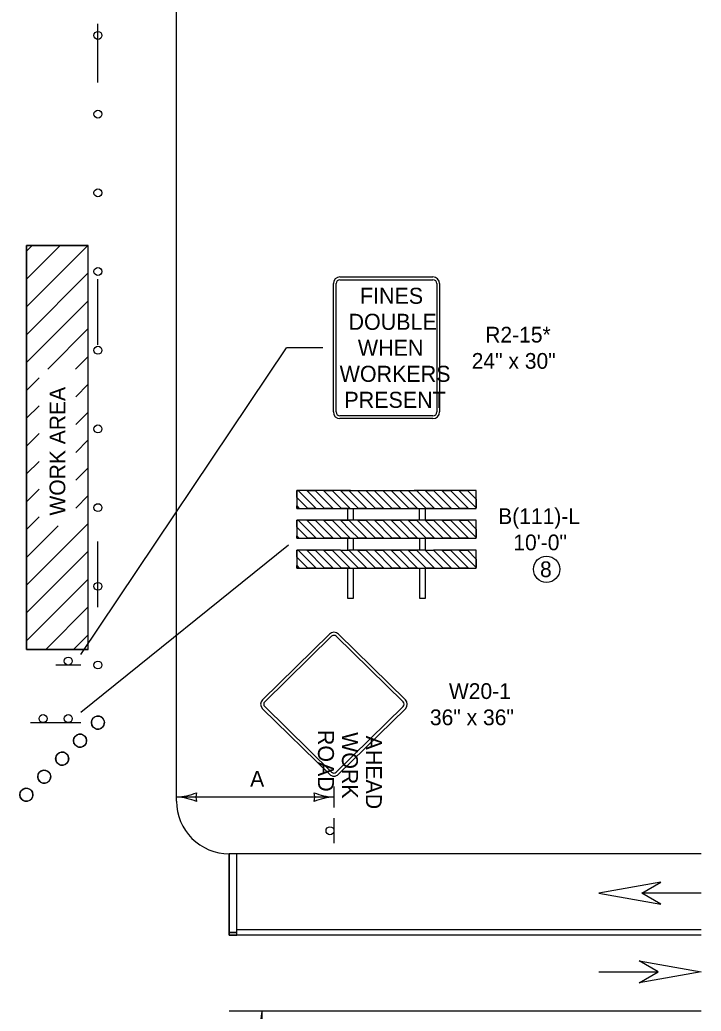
# Model space of a CAD drawing. Extents: x 49991.4 to 50021, y 49987.6 to 50011.4.
# Drawn here: x 50001.828 to 50004.426, y 49992.224 to 49996.003 of the extents above; entities that cross this region are included whole.
import ezdxf

# ---------------------------------------------------------------- set-up
doc = ezdxf.new("R2010")
doc.units = 0
for name, color, linetype in [('Level 1', 7, 'Continuous'), ('Level 2', 7, 'Continuous'), ('Level 3', 7, 'Continuous')]:
    doc.layers.add(name, color=color, linetype=linetype)

msp = doc.modelspace()

# ---------------------------------------------------------------- linework, layer by layer
at = {"layer": 'Level 1'}
for p, q in [((50002.4258, 49995.0313), (50002.4258, 49998.8719)), ((50002.1259, 49995.764), (50002.1259, 49995.988)), ((50001.8536, 49993.6029), (50001.8536, 49995.1428)), ((50001.8536, 49995.1428), (50002.0891, 49995.1428)), ((50001.8536, 49995.1207), (50001.8757, 49995.1428)), ((50001.8536, 49995.0146), (50001.9818, 49995.1428)), ((50001.8536, 49994.9086), (50002.0878, 49995.1428)), ((50002.0891, 49993.6029), (50002.0891, 49995.1428)), ((50001.8536, 49994.8025), (50002.0891, 49995.038)), ((50002.1259, 49994.764), (50002.1259, 49995.014)), ((50002.4258, 49993.024), (50002.4258, 49995.0313)), ((50003.0487, 49995.0228), (50003.4031, 49995.0228)), ((50003.0487, 49995.0123), (50003.4031, 49995.0123)), ((50003.2259, 49995.0228), (50003.2259, 49995.0228)), ((50003.0234, 49994.5081), (50003.0234, 49994.9975)), ((50003.034, 49994.5081), (50003.034, 49994.9975)), ((50003.4179, 49994.9975), (50003.4179, 49994.5081)), ((50003.4285, 49994.9975), (50003.4285, 49994.5081)), ((50001.8536, 49994.6964), (50002.0891, 49994.9319)), ((50001.9345, 49994.6712), (50002.0891, 49994.8259)), ((50002.0406, 49994.6712), (50002.0891, 49994.7198)), ((50001.8536, 49994.5904), (50001.9014, 49994.6381)), ((50002.0414, 49994.566), (50002.0891, 49994.6137)), ((50001.8536, 49994.4843), (50001.9014, 49994.5321)), ((50002.0414, 49994.4599), (50002.0891, 49994.5077)), ((50003.4031, 49994.4933), (50003.0487, 49994.4933)), ((50003.4031, 49994.4827), (50003.0487, 49994.4827)), ((50001.8536, 49994.3783), (50001.9014, 49994.426)), ((50002.0414, 49994.3539), (50002.0891, 49994.4016)), ((50001.8536, 49994.2722), (50001.9014, 49994.3199)), ((50002.0414, 49994.2478), (50002.0891, 49994.2956)), ((50001.8536, 49994.1661), (50001.9014, 49994.2139)), ((50002.0414, 49994.1417), (50002.0891, 49994.1895)), ((50002.9257, 49994.1407), (50002.884, 49994.1824)), ((50002.9257, 49994.1407), (50002.884, 49994.1824)), ((50002.9579, 49994.1407), (50002.8895, 49994.2091)), ((50002.8895, 49994.2091), (50002.9579, 49994.1407)), ((50002.9902, 49994.1407), (50002.9218, 49994.2091)), ((50002.9902, 49994.1407), (50002.9218, 49994.2091)), ((50003.0225, 49994.1407), (50002.9541, 49994.2091)), ((50002.9541, 49994.2091), (50003.0225, 49994.1407)), ((50003.0547, 49994.1407), (50002.9863, 49994.2091)), ((50003.0547, 49994.1407), (50002.9863, 49994.2091)), ((50003.0869, 49994.1407), (50003.0185, 49994.2091)), ((50003.0185, 49994.2091), (50003.0869, 49994.1407)), ((50003.1192, 49994.1407), (50003.0508, 49994.2091)), ((50003.1514, 49994.1407), (50003.083, 49994.2091)), ((50003.083, 49994.2091), (50003.1229, 49994.2091)), ((50003.1034, 49994.2091), (50003.3485, 49994.2091)), ((50003.1836, 49994.1407), (50003.1152, 49994.2091)), ((50003.2158, 49994.1407), (50003.1474, 49994.2091)), ((50003.248, 49994.1407), (50003.1796, 49994.2091)), ((50003.2802, 49994.1407), (50003.2118, 49994.2091)), ((50003.3124, 49994.1407), (50003.244, 49994.2091)), ((50003.3446, 49994.1407), (50003.2762, 49994.2091)), ((50003.377, 49994.1407), (50003.3086, 49994.2091)), ((50003.3627, 49994.2091), (50003.3314, 49994.2091)), ((50003.4093, 49994.1407), (50003.3409, 49994.2091)), ((50003.4415, 49994.1407), (50003.3732, 49994.2091)), ((50003.4415, 49994.1407), (50003.3732, 49994.2091)), ((50003.4737, 49994.1407), (50003.4054, 49994.2091)), ((50003.4054, 49994.2091), (50003.4737, 49994.1407)), ((50003.506, 49994.1407), (50003.4376, 49994.2091)), ((50003.506, 49994.1407), (50003.4376, 49994.2091)), ((50003.5382, 49994.1407), (50003.4698, 49994.2091)), ((50003.4698, 49994.2091), (50003.5382, 49994.1407)), ((50003.5679, 49994.1432), (50003.5021, 49994.2091)), ((50003.5679, 49994.1432), (50003.5021, 49994.2091)), ((50003.5679, 49994.1755), (50003.5343, 49994.2091)), ((50003.5343, 49994.2091), (50003.5679, 49994.1755)), ((50002.8935, 49994.1407), (50002.884, 49994.1502)), ((50002.884, 49994.1502), (50002.8935, 49994.1407)), ((50001.8536, 49994.0601), (50001.9014, 49994.1078)), ((50003.1005, 49994.0951), (50003.1005, 49994.1407)), ((50003.3513, 49994.0951), (50003.3513, 49994.1407)), ((50001.8536, 49993.8479), (50002.0891, 49994.0834)), ((50001.8536, 49993.954), (50001.9741, 49994.0744)), ((50002.9257, 49994.0267), (50002.884, 49994.0685)), ((50002.9257, 49994.0267), (50002.884, 49994.0685)), ((50002.9579, 49994.0267), (50002.8895, 49994.0951)), ((50002.8895, 49994.0951), (50002.9579, 49994.0267)), ((50002.9902, 49994.0267), (50002.9218, 49994.0951)), ((50002.9902, 49994.0267), (50002.9218, 49994.0951)), ((50003.0225, 49994.0267), (50002.9541, 49994.0951)), ((50002.9541, 49994.0951), (50003.0225, 49994.0267)), ((50003.0547, 49994.0267), (50002.9863, 49994.0951)), ((50003.0547, 49994.0267), (50002.9863, 49994.0951)), ((50003.0869, 49994.0267), (50003.0185, 49994.0951)), ((50003.0185, 49994.0951), (50003.0869, 49994.0267)), ((50003.0891, 49994.0568), (50003.0508, 49994.0951)), ((50003.0891, 49994.089), (50003.083, 49994.0951)), ((50003.1514, 49994.0267), (50003.0891, 49994.089)), ((50003.1836, 49994.0267), (50003.1152, 49994.0951)), ((50003.2158, 49994.0267), (50003.1475, 49994.0951)), ((50003.2481, 49994.0267), (50003.1797, 49994.0951)), ((50003.2804, 49994.0267), (50003.212, 49994.0951)), ((50003.3126, 49994.0267), (50003.2442, 49994.0951)), ((50003.3448, 49994.0267), (50003.2764, 49994.0951)), ((50003.377, 49994.0267), (50003.3086, 49994.0951)), ((50003.4093, 49994.0267), (50003.3409, 49994.0951)), ((50003.4415, 49994.0267), (50003.3732, 49994.0951)), ((50003.4415, 49994.0267), (50003.3732, 49994.0951)), ((50003.4737, 49994.0267), (50003.4054, 49994.0951)), ((50003.4054, 49994.0951), (50003.4737, 49994.0267)), ((50003.506, 49994.0267), (50003.4376, 49994.0951)), ((50003.506, 49994.0267), (50003.4376, 49994.0951)), ((50003.5382, 49994.0267), (50003.4698, 49994.0951)), ((50003.4698, 49994.0951), (50003.5382, 49994.0267)), ((50003.5679, 49994.0293), (50003.5021, 49994.0951)), ((50003.5679, 49994.0293), (50003.5021, 49994.0951)), ((50003.5679, 49994.0615), (50003.5343, 49994.0951)), ((50003.5343, 49994.0951), (50003.5679, 49994.0615)), ((50002.8935, 49994.0267), (50002.884, 49994.0363)), ((50002.884, 49994.0363), (50002.8935, 49994.0267)), ((50003.1192, 49994.0267), (50003.0891, 49994.0568)), ((50002.1259, 49993.764), (50002.1259, 49994.014)), ((50001.8536, 49993.7419), (50002.0891, 49993.9774)), ((50002.9257, 49993.9128), (50002.884, 49993.9545)), ((50002.9257, 49993.9128), (50002.884, 49993.9545)), ((50002.9579, 49993.9128), (50002.8895, 49993.9812)), ((50002.8895, 49993.9812), (50002.9579, 49993.9128)), ((50002.9902, 49993.9128), (50002.9218, 49993.9812)), ((50002.9902, 49993.9128), (50002.9218, 49993.9812)), ((50003.0225, 49993.9128), (50002.9541, 49993.9812)), ((50002.9541, 49993.9812), (50003.0225, 49993.9128)), ((50003.0547, 49993.9128), (50002.9863, 49993.9812)), ((50003.0547, 49993.9128), (50002.9863, 49993.9812)), ((50003.0869, 49993.9128), (50003.0185, 49993.9812)), ((50003.0185, 49993.9812), (50003.0869, 49993.9128)), ((50003.1192, 49993.9128), (50003.0508, 49993.9812)), ((50003.1192, 49993.9128), (50003.0508, 49993.9812)), ((50003.1514, 49993.9128), (50003.083, 49993.9812)), ((50003.083, 49993.9812), (50003.1514, 49993.9128)), ((50003.1836, 49993.9128), (50003.1152, 49993.9812)), ((50003.1836, 49993.9128), (50003.1152, 49993.9812)), ((50003.2158, 49993.9128), (50003.1475, 49993.9812)), ((50003.1475, 49993.9812), (50003.2158, 49993.9128)), ((50003.2481, 49993.9128), (50003.1797, 49993.9812)), ((50003.2481, 49993.9128), (50003.1797, 49993.9812)), ((50003.2804, 49993.9128), (50003.212, 49993.9812)), ((50003.212, 49993.9812), (50003.2804, 49993.9128)), ((50003.3126, 49993.9128), (50003.2442, 49993.9812)), ((50003.3126, 49993.9128), (50003.2442, 49993.9812)), ((50003.3448, 49993.9128), (50003.2764, 49993.9812)), ((50003.2764, 49993.9812), (50003.3448, 49993.9128)), ((50003.377, 49993.9128), (50003.3086, 49993.9812)), ((50003.377, 49993.9128), (50003.3086, 49993.9812)), ((50003.4093, 49993.9128), (50003.3409, 49993.9812)), ((50003.3409, 49993.9812), (50003.4093, 49993.9128)), ((50003.4415, 49993.9128), (50003.3732, 49993.9812)), ((50003.4415, 49993.9128), (50003.3732, 49993.9812)), ((50003.4737, 49993.9128), (50003.4054, 49993.9812)), ((50003.4054, 49993.9812), (50003.4737, 49993.9128)), ((50003.506, 49993.9128), (50003.4376, 49993.9812)), ((50003.506, 49993.9128), (50003.4376, 49993.9812)), ((50003.5382, 49993.9128), (50003.4698, 49993.9812)), ((50003.4698, 49993.9812), (50003.5382, 49993.9128)), ((50003.5679, 49993.9153), (50003.5021, 49993.9812)), ((50003.5679, 49993.9153), (50003.5021, 49993.9812)), ((50003.5679, 49993.9476), (50003.5343, 49993.9812)), ((50003.5343, 49993.9812), (50003.5679, 49993.9476)), ((50002.8935, 49993.9128), (50002.884, 49993.9223)), ((50002.884, 49993.9223), (50002.8935, 49993.9128)), ((50001.8536, 49993.6358), (50002.0891, 49993.8713)), ((50001.9268, 49993.6029), (50002.0891, 49993.7652)), ((50002.0328, 49993.6029), (50002.0891, 49993.6592)), ((50002.7534, 49993.4113), (50003.0086, 49993.6613)), ((50002.7616, 49993.4029), (50003.0168, 49993.653)), ((50003.0346, 49993.653), (50003.2899, 49993.4029)), ((50003.0428, 49993.6613), (50003.2981, 49993.4113)), ((50002.0891, 49993.6029), (50001.8536, 49993.6029)), ((50002.0608, 49993.5435), (50001.9648, 49993.5435)), ((50003.0086, 49993.127), (50002.7534, 49993.377)), ((50003.0168, 49993.1353), (50002.7616, 49993.3854)), ((50003.2899, 49993.3854), (50003.0346, 49993.1353)), ((50003.2981, 49993.377), (50003.0428, 49993.127)), ((50001.8688, 49993.3239), (50001.9648, 49993.3239)), ((50001.9648, 49993.3239), (50002.0608, 49993.3239)), ((50001.863, 49993.024), (50001.863, 49993.0261)), ((50003.0258, 49992.96), (50003.0258, 49992.864)), ((50004.4258, 49992.824), (50002.6258, 49992.824)), ((50002.6258, 49992.5141), (50002.6258, 49992.824)), ((50002.6558, 49992.5141), (50002.6558, 49992.824)), ((50004.4258, 49992.6741), (50004.1999, 49992.6741)), ((50004.4258, 49992.6737), (50004.1999, 49992.6737)), ((50002.6558, 49992.5241), (50002.6258, 49992.5241)), ((50004.4258, 49992.5341), (50002.6558, 49992.5341)), ((50004.4258, 49992.5141), (50002.6258, 49992.5141)), ((50004.0357, 49992.3741), (50004.2616, 49992.3741)), ((50004.0357, 49992.3737), (50004.2616, 49992.3737)), ((50004.4258, 49992.224), (50002.6258, 49992.224))]:
    msp.add_line(p, q, dxfattribs=at)
for points in [[(50002.0891, 49993.6029), (50002.0891, 49995.1428), (50001.8536, 49995.1428), (50001.8536, 49993.6029), (50002.0891, 49993.6029)], [(50003.0891, 49994.2091), (50002.884, 49994.2091), (50002.884, 49994.1407), (50003.0891, 49994.1407)], [(50002.884, 49994.1824), (50002.884, 49994.2091), (50002.8895, 49994.2091)], [(50002.9218, 49994.2091), (50002.9541, 49994.2091)], [(50002.9863, 49994.2091), (50003.0185, 49994.2091)], [(50003.1514, 49994.1407), (50003.1192, 49994.1407), (50003.0508, 49994.2091), (50003.083, 49994.2091), (50003.1514, 49994.1407)], [(50003.0891, 49994.1407), (50003.5679, 49994.1407), (50003.5679, 49994.2091), (50003.3627, 49994.2091)], [(50003.1152, 49994.2091), (50003.1229, 49994.2091), (50003.1474, 49994.2091), (50003.2158, 49994.1407), (50003.1836, 49994.1407), (50003.1152, 49994.2091)], [(50003.1796, 49994.2091), (50003.2118, 49994.2091), (50003.2802, 49994.1407), (50003.248, 49994.1407), (50003.1796, 49994.2091)], [(50003.244, 49994.2091), (50003.2762, 49994.2091), (50003.3446, 49994.1407), (50003.3124, 49994.1407), (50003.244, 49994.2091)], [(50003.3086, 49994.2091), (50003.3314, 49994.2091), (50003.3409, 49994.2091), (50003.4093, 49994.1407), (50003.377, 49994.1407), (50003.3086, 49994.2091)], [(50003.3732, 49994.2091), (50003.4054, 49994.2091)], [(50003.4376, 49994.2091), (50003.4698, 49994.2091)], [(50003.5021, 49994.2091), (50003.5343, 49994.2091)], [(50002.8935, 49994.1407), (50002.884, 49994.1407), (50002.884, 49994.1502)], [(50003.5679, 49994.1755), (50003.5679, 49994.1432)], [(50002.9579, 49994.1407), (50002.9257, 49994.1407)], [(50003.0225, 49994.1407), (50002.9902, 49994.1407)], [(50003.0869, 49994.1407), (50003.0547, 49994.1407)], [(50003.0777, 49994.1407), (50003.0777, 49994.0951)], [(50003.3741, 49994.0951), (50003.3741, 49994.1407)], [(50003.4737, 49994.1407), (50003.4415, 49994.1407)], [(50003.5382, 49994.1407), (50003.506, 49994.1407)], [(50003.0891, 49994.0951), (50002.884, 49994.0951), (50002.884, 49994.0267), (50003.5679, 49994.0267), (50003.5679, 49994.0951), (50003.0891, 49994.0951)], [(50002.884, 49994.0685), (50002.884, 49994.0951), (50002.8895, 49994.0951)], [(50002.9218, 49994.0951), (50002.9541, 49994.0951)], [(50002.9863, 49994.0951), (50003.0185, 49994.0951)], [(50003.1514, 49994.0267), (50003.1192, 49994.0267), (50003.0891, 49994.0568), (50003.0508, 49994.0951), (50003.0777, 49994.0951), (50003.083, 49994.0951), (50003.0891, 49994.089), (50003.1514, 49994.0267)], [(50003.1152, 49994.0951), (50003.1475, 49994.0951), (50003.2158, 49994.0267), (50003.1836, 49994.0267), (50003.1152, 49994.0951)], [(50003.1797, 49994.0951), (50003.212, 49994.0951), (50003.2804, 49994.0267), (50003.2481, 49994.0267), (50003.1797, 49994.0951)], [(50003.2442, 49994.0951), (50003.2764, 49994.0951), (50003.3448, 49994.0267), (50003.3126, 49994.0267), (50003.2442, 49994.0951)], [(50003.3086, 49994.0951), (50003.3409, 49994.0951), (50003.4093, 49994.0267), (50003.377, 49994.0267), (50003.3086, 49994.0951)], [(50003.3732, 49994.0951), (50003.4054, 49994.0951)], [(50003.4376, 49994.0951), (50003.4698, 49994.0951)], [(50003.5021, 49994.0951), (50003.5343, 49994.0951)], [(50002.8935, 49994.0267), (50002.884, 49994.0267), (50002.884, 49994.0363)], [(50003.5679, 49994.0615), (50003.5679, 49994.0293)], [(50002.9579, 49994.0267), (50002.9257, 49994.0267)], [(50003.0225, 49994.0267), (50002.9902, 49994.0267)], [(50003.0869, 49994.0267), (50003.0547, 49994.0267)], [(50003.0777, 49994.0267), (50003.0777, 49993.9812)], [(50003.1005, 49993.9812), (50003.1005, 49994.0267)], [(50003.3513, 49994.0267), (50003.3513, 49993.9812)], [(50003.3741, 49993.9812), (50003.3741, 49994.0267)], [(50003.4737, 49994.0267), (50003.4415, 49994.0267)], [(50003.5382, 49994.0267), (50003.506, 49994.0267)], [(50002.884, 49993.9545), (50002.884, 49993.9812), (50002.8895, 49993.9812)], [(50003.0508, 49993.9812), (50002.884, 49993.9812), (50002.884, 49993.9128), (50003.5679, 49993.9128), (50003.5679, 49993.9812), (50003.4054, 49993.9812)], [(50002.9218, 49993.9812), (50002.9541, 49993.9812)], [(50002.9863, 49993.9812), (50003.0185, 49993.9812)], [(50003.0508, 49993.9812), (50003.083, 49993.9812)], [(50003.3732, 49993.9812), (50003.083, 49993.9812)], [(50003.1152, 49993.9812), (50003.1475, 49993.9812)], [(50003.1797, 49993.9812), (50003.212, 49993.9812)], [(50003.2442, 49993.9812), (50003.2764, 49993.9812)], [(50003.3086, 49993.9812), (50003.3409, 49993.9812)], [(50003.3732, 49993.9812), (50003.4054, 49993.9812)], [(50003.4376, 49993.9812), (50003.4698, 49993.9812)], [(50003.5021, 49993.9812), (50003.5343, 49993.9812)], [(50002.8935, 49993.9128), (50002.884, 49993.9128), (50002.884, 49993.9223)], [(50003.5679, 49993.9476), (50003.5679, 49993.9153)], [(50002.9579, 49993.9128), (50002.9257, 49993.9128)], [(50003.0225, 49993.9128), (50002.9902, 49993.9128)], [(50003.0869, 49993.9128), (50003.0547, 49993.9128)], [(50003.0777, 49993.9127), (50003.0777, 49993.7987), (50003.1005, 49993.7987), (50003.1005, 49993.9127)], [(50003.1514, 49993.9128), (50003.1192, 49993.9128)], [(50003.2158, 49993.9128), (50003.1836, 49993.9128)], [(50003.2804, 49993.9128), (50003.2481, 49993.9128)], [(50003.3448, 49993.9128), (50003.3126, 49993.9128)], [(50003.3513, 49993.9127), (50003.3513, 49993.7987), (50003.3741, 49993.7987), (50003.3741, 49993.9127)], [(50003.4093, 49993.9128), (50003.377, 49993.9128)], [(50003.4737, 49993.9128), (50003.4415, 49993.9128)], [(50003.5382, 49993.9128), (50003.506, 49993.9128)], [(50002.6558, 49992.824), (50002.6258, 49992.824), (50002.6258, 49992.5241), (50002.6558, 49992.5241), (50002.6558, 49992.824)], [(50002.6258, 49992.5141), (50002.6558, 49992.5141), (50002.6558, 49992.5241), (50002.6258, 49992.5241), (50002.6258, 49992.5141)]]:
    msp.add_lwpolyline(points, dxfattribs=at)
for points in [[(50004.2722, 49992.7157), (50004.0357, 49992.6741), (50004.2722, 49992.6321), (50004.2, 49992.6741)], [(50004.1893, 49992.4157), (50004.4258, 49992.3741), (50004.1893, 49992.3321), (50004.2615, 49992.3741)]]:
    msp.add_lwpolyline(points, close=True, dxfattribs=at)
for centre, radius in [((50002.1258, 49995.9435), 0.015), ((50002.1258, 49995.6435), 0.015), ((50002.1258, 49995.3435), 0.015), ((50002.1258, 49995.0435), 0.015), ((50002.1258, 49994.7435), 0.015), ((50002.1258, 49994.4435), 0.015), ((50002.1258, 49994.1435), 0.015), ((50002.1258, 49993.8435), 0.015), ((50002.0128, 49993.5586), 0.0152), ((50002.1258, 49993.5435), 0.015), ((50001.9168, 49993.3391), 0.0152), ((50002.0128, 49993.3391), 0.0152), ((50002.1258, 49993.3239), 0.025), ((50002.0576, 49993.2552), 0.025), ((50001.9894, 49993.1865), 0.025), ((50001.9212, 49993.1177), 0.025), ((50001.853, 49993.049), 0.025), ((50001.853, 49993.049), 0.025), ((50003.0106, 49992.9119), 0.0152)]:
    msp.add_circle(centre, radius, dxfattribs=at)
for centre, radius, start, end in [((50003.0487, 49994.9975), 0.0253, 90, 180), ((50003.0487, 49994.9975), 0.0148, 90, 180), ((50003.4031, 49994.9975), 0.0253, 0, 90), ((50003.4031, 49994.9975), 0.0148, 0, 90), ((50003.0487, 49994.5081), 0.0253, 180, 270), ((50003.0487, 49994.5081), 0.0148, 180, 270), ((50003.4031, 49994.5081), 0.0148, 270, 360), ((50003.4031, 49994.5081), 0.0253, 270, 360), ((50002.1258, 49993.3239), 0.025, 99.0657, 279.0657), ((50002.1258, 49993.3239), 0.025, 279.0657, 99.0657), ((50002.0576, 49993.2552), 0.025, 99.0657, 279.0657), ((50002.0576, 49993.2552), 0.025, 279.0657, 99.0657), ((50001.9894, 49993.1865), 0.025, 99.0657, 279.0657), ((50001.9894, 49993.1865), 0.025, 279.0657, 99.0657), ((50001.9212, 49993.1177), 0.025, 99.0657, 279.0657), ((50001.9212, 49993.1177), 0.025, 279.0657, 99.0657), ((50001.853, 49993.049), 0.025, 99.0657, 279.0657), ((50001.853, 49993.049), 0.025, 99.0657, 279.0657), ((50001.853, 49993.049), 0.025, 279.0657, 99.0657), ((50001.853, 49993.049), 0.025, 279.0657, 99.0657), ((50002.6258, 49993.024), 0.2, 180, 270.0006)]:
    msp.add_arc(centre, radius, start, end, dxfattribs=at)
for centre, major_axis, ratio, start_param, end_param in [((50003.0258, 49993.6443), (-0.0243, 0), 0.98963, 3.926991, 5.497787), ((50003.0258, 49993.6443), (-0.0126, 0), 0.98, 3.926991, 5.497787), ((50002.7705, 49993.3941), (-0.0243, 0), 0.98963, 5.497787, 7.068583), ((50002.7705, 49993.3941), (-0.0126, 0), 0.98, 5.497787, 7.068583), ((50003.281, 49993.3941), (0.0126, 0), 0.98, 5.497795, 7.068583), ((50003.281, 49993.3941), (0.0243, 0), 0.98963, 5.497795, 7.068583), ((50003.0258, 49993.144), (-0.0243, 0), 0.98963, 0.785394, 2.356194), ((50003.0258, 49993.144), (-0.0126, 0), 0.98, 0.785394, 2.356194)]:
    msp.add_ellipse(centre, major_axis=major_axis, ratio=ratio, start_param=start_param, end_param=end_param, dxfattribs=at)
at = {"layer": 'Level 2'}
msp.add_circle((50003.8363, 49993.9085), 0.0501, dxfattribs=at)
at = {"layer": 'Level 3'}
for p, q in [((50002.0608, 49993.5835), (50002.8451, 49994.7528)), ((50002.9834, 49994.7528), (50002.8451, 49994.7528)), ((50002.0608, 49993.3639), (50002.8528, 49994.0016)), ((50003.0258, 49993.08), (50003.0258, 49993)), ((50003.0258, 49993.04), (50002.4258, 49993.04)), ((50002.7518, 49991.4057), (50002.7518, 49992.224))]:
    msp.add_line(p, q, dxfattribs=at)
for centre, radius, start, end in [((50002.4143, 49993.2727), 0.233, 272.8273, 292.0772), ((50002.554, 49993.04), 0.0548, 162.1388, 197.8612), ((50003.0349, 49993.2621), 0.2223, 247.456, 267.6395), ((50002.8976, 49993.04), 0.0548, 342.1388, 17.8612), ((50002.4166, 49992.8179), 0.2223, 67.456, 87.6395), ((50003.0373, 49992.8073), 0.233, 92.8273, 112.0772), ((50002.5296, 49992.2331), 0.2223, 337.456, 357.6395)]:
    msp.add_arc(centre, radius, start, end, dxfattribs=at)

# ---------------------------------------------------------------- texts
at = {"layer": 'Level 1'}
for s, p in [('FINES', (50003.1248, 49994.9205)), ('DOUBLE', (50003.0813, 49994.8213)), ('WHEN', (50003.1168, 49994.7222)), ('WORKERS', (50003.0474, 49994.623)), ('PRESENT', (50003.0655, 49994.5239))]:
    msp.add_text(s, height=0.06118, dxfattribs=at).set_placement(p)
for s, p in [('ROAD', (50002.9649, 49993.2959)), ('WORK', (50003.0562, 49993.2874)), ('AHEAD', (50003.1474, 49993.2744))]:
    msp.add_text(s, height=0.06086, rotation=270, dxfattribs=at).set_placement(p)
at = {"layer": 'Level 2'}
for s, p in [('R2-15*', (50003.6024, 49994.7728)), ('24" x 30"', (50003.5509, 49994.6728)), ('B(111)-L', (50003.6517, 49994.0809)), ('10\'-0"', (50003.7095, 49993.9809)), ('8', (50003.8113, 49993.8785))]:
    msp.add_text(s, height=0.06, dxfattribs=at).set_placement(p)
for s, rotation, p in [('WORK AREA', 90, (50002.0014, 49994.1132)), ('W20-1', 360, (50003.4639, 49993.4141)), ('36" x 36"', 360, (50003.3916, 49993.3141)), ('A', 360, (50002.7062, 49993.08))]:
    msp.add_text(s, height=0.06, rotation=rotation, dxfattribs=at).set_placement(p)

doc.saveas('drawing.dxf')
